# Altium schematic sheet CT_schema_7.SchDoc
size 405 x 220 mm
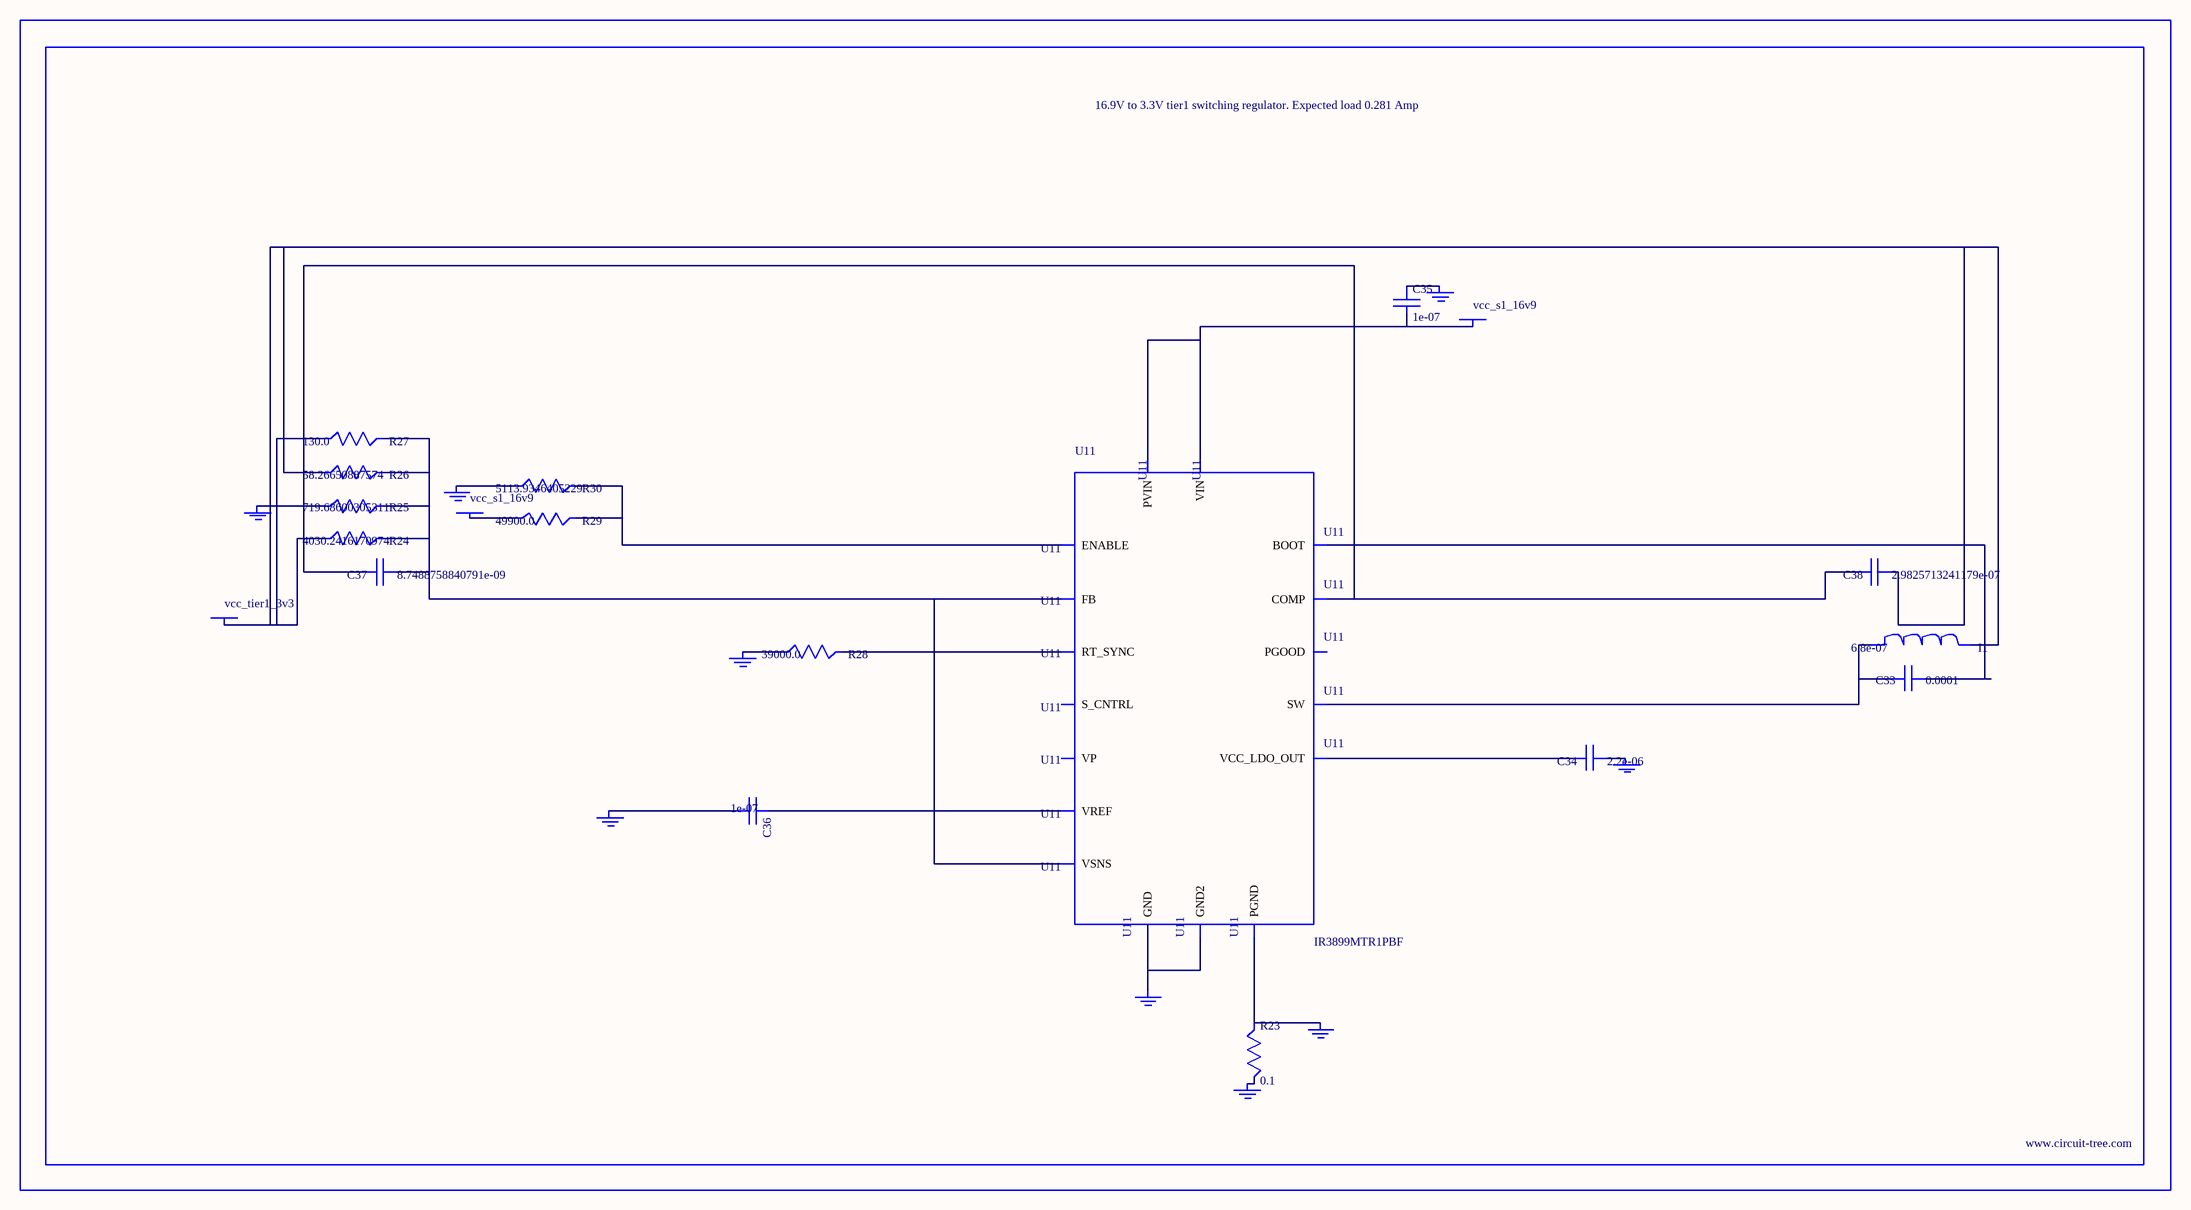
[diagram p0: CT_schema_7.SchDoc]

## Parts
BORDER6  (no value)
C33  0.0001  [C1210]
C34  2.2e-06  [C0603]
C35  1e-07  [C0402]
C36  1e-07  [C0402]
C37  8.7488758840791e-09  [R0603]
C38  2.9825713241179e-07  [R0603]
GND_INSTANCE_6_0  (no value)
GND_INSTANCE_6_1  (no value)
GND_INSTANCE_6_2  (no value)
GND_INSTANCE_6_3  (no value)
GND_INSTANCE_6_4  (no value)
GND_INSTANCE_6_5  (no value)
GND_INSTANCE_6_6  (no value)
GND_INSTANCE_6_7  (no value)
GND_INSTANCE_6_8  (no value)
I1  6.8e-07  [IND25X25CZ]
POWER_INSTANCE_6_0  vcc_s1_16v9
POWER_INSTANCE_6_1  vcc_s1_16v9
POWER_INSTANCE_6_2  vcc_tier1_3v3
R23  0.1  [R0603]
R24  4030.2416170974  [R0603]
R25  719.68600305311  [R0603]
R26  58.26650887574  [R0603]
R27  130.0  [R0603]
R28  39000.0  [R0603]
R29  49900.0  [R0603]
R30  5113.9346405229  [R0603]
U11  IR3899MTR1PBF  [IR3899MTR1PBF]

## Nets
NetC33_1: C33.1 U11.14(BOOT)
NetC33_2: C33.2 I1.1 U11.12(SW)
NetC34_1: C34.1 GND_INSTANCE_6_4.0(GND)
NetC34_2: C34.2 U11.10(VCC_LDO_OUT)
NetC35_1: C35.1 GND_INSTANCE_6_3.0(GND)
NetC35_2: C35.2 POWER_INSTANCE_6_0.0(PWR) U11.9(VIN) U11.13(PVIN)
NetC36_1: C36.1 U11.2(VREF)
NetC36_2: C36.2 GND_INSTANCE_6_1.0(GND)
NetC37_1: C37.1 R24.2 R25.2 R26.2 R27.2 U11.1(FB) U11.8(VSNS)
NetC37_2: C37.2 C38.2 U11.3(COMP)
NetC38_1: C38.1 I1.2 POWER_INSTANCE_6_2.0(PWR) R24.1 R26.1 R27.1
NetGND_INSTANCE_6_0_0: GND_INSTANCE_6_0.0(GND) R25.1
NetGND_INSTANCE_6_2_0: GND_INSTANCE_6_2.0(GND) R28.1
NetGND_INSTANCE_6_5_0: GND_INSTANCE_6_5.0(GND) R23.2
NetGND_INSTANCE_6_6_0: GND_INSTANCE_6_6.0(GND) R23.1 U11.11(PGND)
NetGND_INSTANCE_6_7_0: GND_INSTANCE_6_7.0(GND) R30.1
NetGND_INSTANCE_6_8_0: GND_INSTANCE_6_8.0(GND) U11.4(GND) U11.17(GND2)
NetPOWER_INSTANCE_6_1_0: POWER_INSTANCE_6_1.0(PWR) R29.1
NetR28_2: R28.2 U11.5(RT_SYNC)
NetR29_2: R29.2 R30.2 U11.15(ENABLE)

Not connected (* = marked no-connect by the designer): U11 6(S_CNTRL) 7(PGOOD) 16(VP)

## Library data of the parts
BORDER6 = BORDER_PAGE6
C33 = GRM32ER61A107ME20L
C34 = C0603C225K8RACTU
C35 C36 = C0402C104K3RACTU
C37 = C37
C38 = C38
GND_INSTANCE_6_0-GND_INSTANCE_6_8 = GND
I1 = IHLP2525CZERR68M01
POWER_INSTANCE_6_0-POWER_INSTANCE_6_2 = PWR
R23 = ERJ-3RSFR10V
R24 = R24
R25 = R25
R26 = R26
R27 = RC0603JR-07130RL
R28 = RC0603JR-0739KL
R29 = RC0603FR-0749K9
R30 = R30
